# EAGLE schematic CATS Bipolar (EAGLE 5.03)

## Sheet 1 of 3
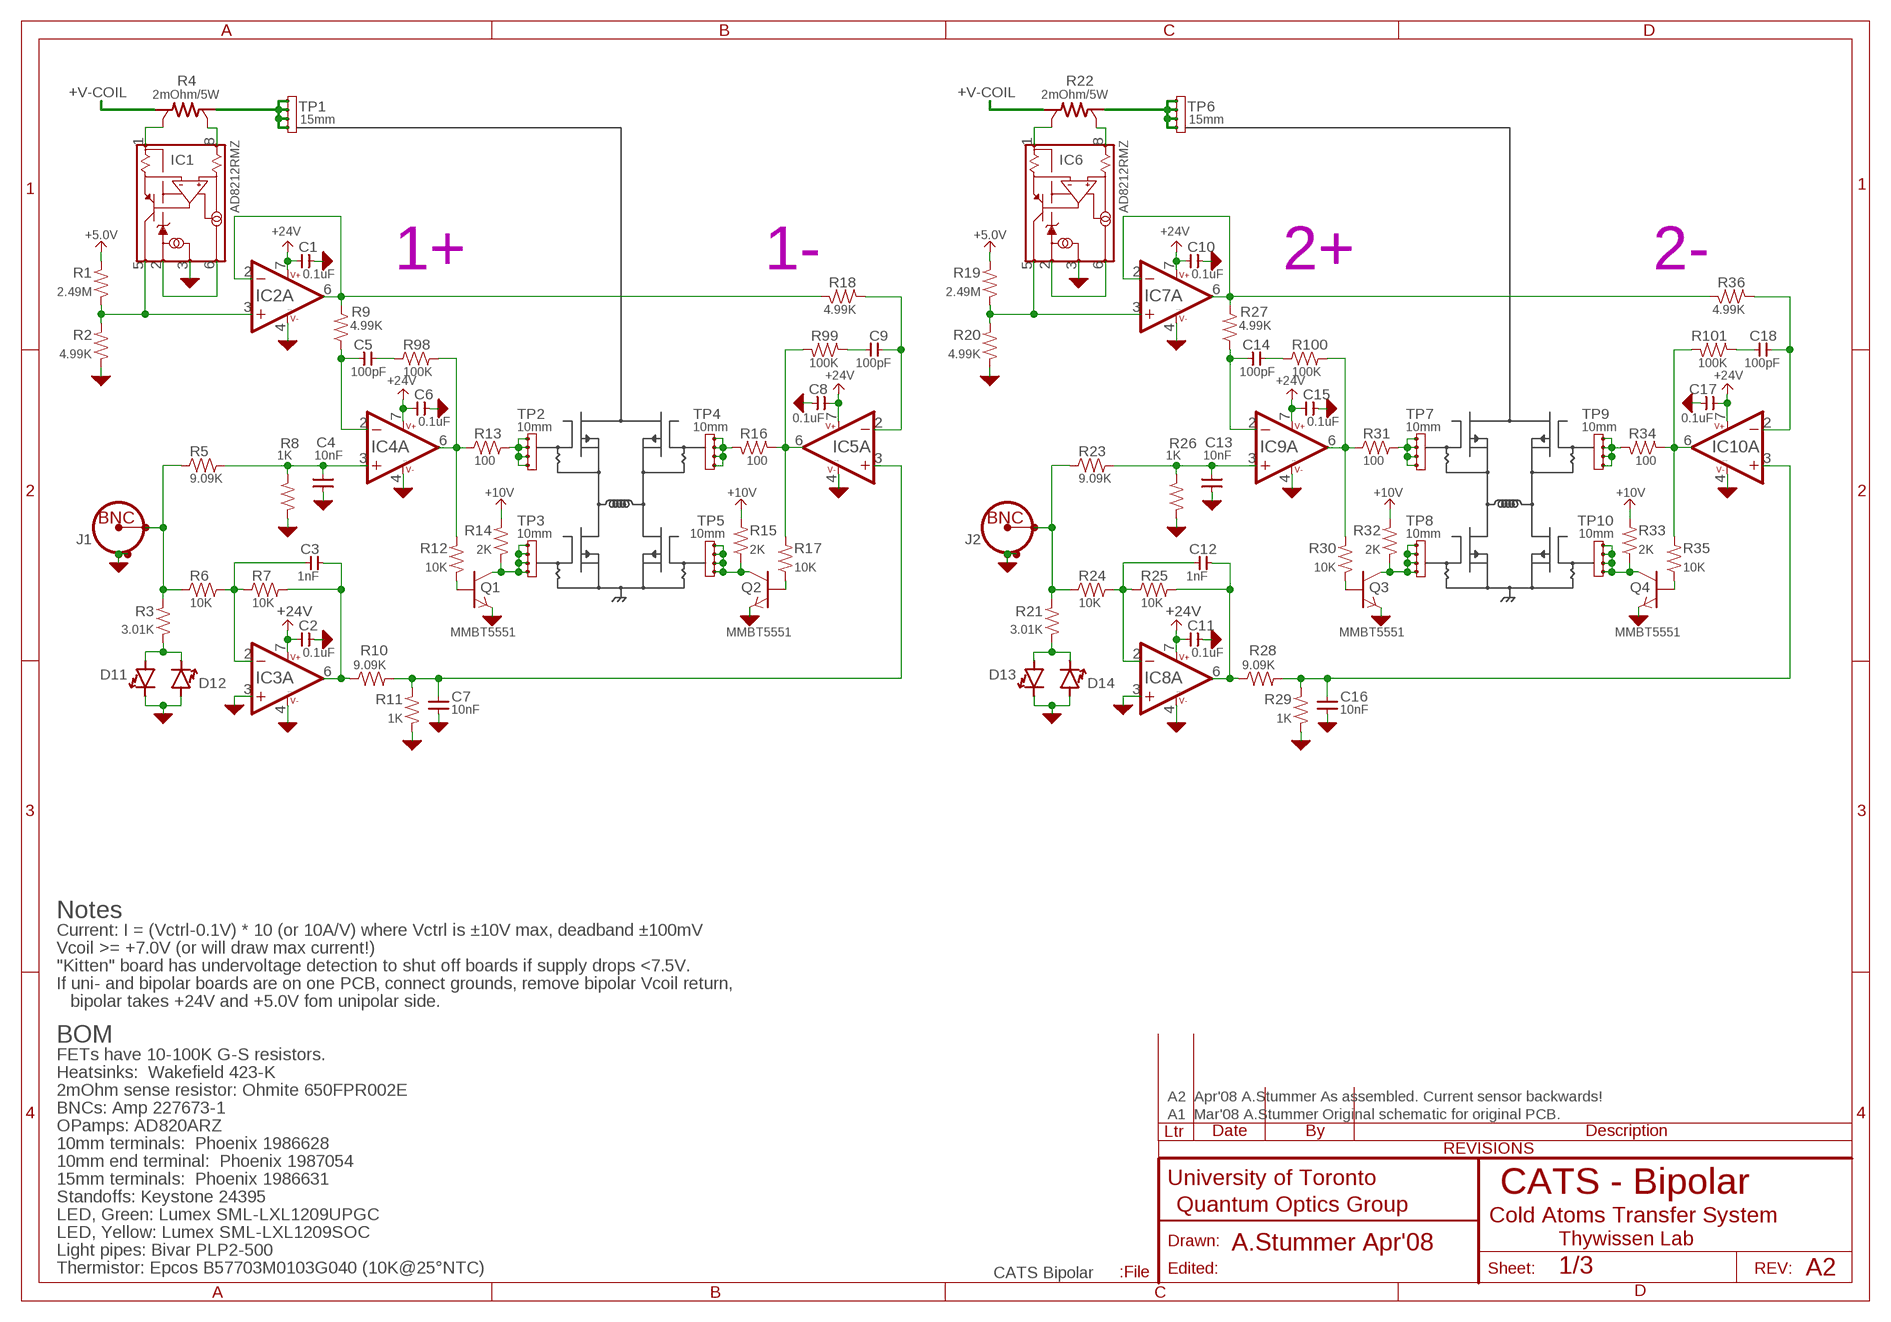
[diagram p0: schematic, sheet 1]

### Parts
C1  0.1uF  CAP-H-0805  [2012(0805)]
C2  0.1uF  CAP-H-0805  [2012(0805)]
C3  1nF  CAP-H-0805  [2012(0805)]
C4  10nF  CAP-V-0805  [2012(0805)]
C5  100pF  CAP-H-0805  [2012(0805)]
C6  0.1uF  CAP-H-0805  [2012(0805)]
C7  10nF  CAP-V-0805  [2012(0805)]
C8  0.1uF  CAP-H-0805  [2012(0805)]
C9  100pF  CAP-H-0805  [2012(0805)]
C10  0.1uF  CAP-H-0805  [2012(0805)]
C11  0.1uF  CAP-H-0805  [2012(0805)]
C12  1nF  CAP-H-0805  [2012(0805)]
C13  10nF  CAP-V-0805  [2012(0805)]
C14  100pF  CAP-H-0805  [2012(0805)]
C15  0.1uF  CAP-H-0805  [2012(0805)]
C16  10nF  CAP-V-0805  [2012(0805)]
C17  0.1uF  CAP-H-0805  [2012(0805)]
C18  100pF  CAP-H-0805  [2012(0805)]
D11  SML-LXL1209UPGC  LED-1209  [1209]
D12  SML-LXL1209SOC  LED-1209  [1209]
D13  SML-LXL1209UPGC  LED-1209  [1209]
D14  SML-LXL1209SOC  LED-1209  [1209]
IC1  AD8212RMZ  AD8212(CURRENT_MONITOR)RMZ  [MSOP8]
IC2  AD820ARZ  OPAMP-SO8  [SOIC-8]
IC3  AD820ARZ  OPAMP-SO8  [SOIC-8]
IC4  AD820ARZ  OPAMP-SO8  [SOIC-8]
IC5  AD820ARZ  OPAMP-SO8  [SOIC-8]
IC6  AD8212RMZ  AD8212(CURRENT_MONITOR)RMZ  [MSOP8]
IC7  AD820ARZ  OPAMP-SO8  [SOIC-8]
IC8  AD820ARZ  OPAMP-SO8  [SOIC-8]
IC9  AD820ARZ  OPAMP-SO8  [SOIC-8]
IC10  AD820ARZ  OPAMP-SO8  [SOIC-8]
J1  Amp 227673-1  CONN-BNC-TYPE1VERT  [CONN-BNC-AMP-TYPE1VERT]
J2  Amp 227673-1  CONN-BNC-TYPE1VERT  [CONN-BNC-AMP-TYPE1VERT]
Q1  MMBT5551  BJT-NPN-SOT23  [SOT23]
Q2  MMBT5551  BJT-NPN-SOT23  [SOT23]
Q3  MMBT5551  BJT-NPN-SOT23  [SOT23]
Q4  MMBT5551  BJT-NPN-SOT23  [SOT23]
R1  2.49M  R-V-0805  [2012(0805)]
R2  4.99K  R-V-0805  [2012(0805)]
R3  3.01K  R-H-0805  [2012(0805)]
R4  2mOhm/5W  R-SENSE-OHMITE_650  [OHMITE_650]
R5  9.09K  R-H-0805  [2012(0805)]
R6  10K  R-H-0805  [2012(0805)]
R7  10K  R-H-0805  [2012(0805)]
R8  1K  R-V-0805  [2012(0805)]
R9  4.99K  R-V-0805  [2012(0805)]
R10  9.09K  R-H-0805  [2012(0805)]
R11  1K  R-V-0805  [2012(0805)]
R12  10K  R-V-0805  [2012(0805)]
R13  100  R-H-0805  [2012(0805)]
R14  2K  R-V-0805  [2012(0805)]
R15  2K  R-V-0805  [2012(0805)]
R16  100  R-H-0805  [2012(0805)]
R17  10K  R-V-0805  [2012(0805)]
R18  4.99K  R-H-0805  [2012(0805)]
R19  2.49M  R-V-0805  [2012(0805)]
R20  4.99K  R-V-0805  [2012(0805)]
R21  3.01K  R-H-0805  [2012(0805)]
R22  2mOhm/5W  R-SENSE-OHMITE_650  [OHMITE_650]
R23  9.09K  R-H-0805  [2012(0805)]
R24  10K  R-H-0805  [2012(0805)]
R25  10K  R-H-0805  [2012(0805)]
R26  1K  R-V-0805  [2012(0805)]
R27  4.99K  R-V-0805  [2012(0805)]
R28  9.09K  R-H-0805  [2012(0805)]
R29  1K  R-V-0805  [2012(0805)]
R30  10K  R-V-0805  [2012(0805)]
R31  100  R-H-0805  [2012(0805)]
R32  2K  R-V-0805  [2012(0805)]
R33  2K  R-V-0805  [2012(0805)]
R34  100  R-H-0805  [2012(0805)]
R35  10K  R-V-0805  [2012(0805)]
R36  4.99K  R-H-0805  [2012(0805)]
R98  100K  R-H-0805  [2012(0805)]
R99  100K  R-H-0805  [2012(0805)]
R100  100K  R-H-0805  [2012(0805)]
R101  100K  R-H-0805  [2012(0805)]
TP1  Pheonix-1987631  TP4-ZFKDS(10MM)  [PHEONIX_ZFKDS-10/15MM-TERMINAL-BLOCK]
TP2  Pheonix-1987628  TP4-ZFKDS(10MM)  [PHEONIX_ZFKDS-10/15MM-TERMINAL-BLOCK]
TP3  Pheonix-1987628  TP4-ZFKDS(10MM)  [PHEONIX_ZFKDS-10/15MM-TERMINAL-BLOCK]
TP4  Pheonix-1987628  TP4-ZFKDS(10MM)  [PHEONIX_ZFKDS-10/15MM-TERMINAL-BLOCK]
TP5  Pheonix-1987628  TP4-ZFKDS(10MM)  [PHEONIX_ZFKDS-10/15MM-TERMINAL-BLOCK]
TP6  Pheonix-1987631  TP4-ZFKDS(10MM)  [PHEONIX_ZFKDS-10/15MM-TERMINAL-BLOCK]
TP7  Pheonix-1987628  TP4-ZFKDS(10MM)  [PHEONIX_ZFKDS-10/15MM-TERMINAL-BLOCK]
TP8  Pheonix-1987628  TP4-ZFKDS(10MM)  [PHEONIX_ZFKDS-10/15MM-TERMINAL-BLOCK]
TP9  Pheonix-1987628  TP4-ZFKDS(10MM)  [PHEONIX_ZFKDS-10/15MM-TERMINAL-BLOCK]
TP10  Pheonix-1987628  TP4-ZFKDS(10MM)  [PHEONIX_ZFKDS-10/15MM-TERMINAL-BLOCK]

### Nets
+5.0V: R1.2 R19.2 ; also sheet 2,3
+10V: R14.2 R15.2 R32.2 R33.2 ; also sheet 2,3
+24V: C1.1 C2.1 C6.1 C8.1 C10.1 C11.1 C15.1 C17.1 IC2.7(B:V+) IC3.7(B:V+) IC4.7(B:V+) IC5.7(B:V+) IC7.7(B:V+) IC8.7(B:V+) IC9.7(B:V+) IC10.7(B:V+) ; also sheet 2,3
+V-COIL [Power]: R4.CURRENT1 R22.CURRENT1 ; also sheet 2,3
AGND: C1.2 C2.2 C4.1 C6.2 C7.1 C8.2 C10.2 C11.2 C13.1 C15.2 C16.1 C17.2 D11.K(C) D12.A D13.K(C) D14.A IC1.3(BIAS) IC2.4(B:V-) IC3.3(A:+IN) IC3.4(B:V-) IC4.4(B:V-) IC5.4(B:V-) IC6.3(BIAS) IC7.4(B:V-) IC8.3(A:+IN) IC8.4(B:V-) IC9.4(B:V-) IC10.4(B:V-) J1.SHIELD1 J1.SHIELD2 J2.SHIELD1 J2.SHIELD2 Q1.2(E) Q2.2(E) Q3.2(E) Q4.2(E) R2.1 R8.1 R11.1 R20.1 R26.1 R29.1 ; also sheet 2,3
N$1: IC1.5(I-OUT) IC2.3(A:+IN) R1.1 R2.2
N$2: IC2.2(A:-IN) IC2.6(A:OUT) R9.2 R18.2
N$3: IC1.1(V+) R4.SENSE1
N$4: IC1.8(V-SENSE) R4.SENSE2
N$5: IC1.2(COM) IC1.6(ALPHA)
N$6: J1.CONDUCTOR R3.2 R5.1 R6.1
N$7: C9.1 IC5.2(A:-IN) R18.1
N$8 [Power]: R4.CURRENT2 TP1.T@1(T) TP1.T@2(T) TP1.T@3(T) TP1.T@4(T)
N$9: IC5.6(A:OUT) R16.1 R17.2 R99.2
N$10: R16.2 TP4.T@1(T) TP4.T@2(T) TP4.T@3(T) TP4.T@4(T)
N$11: C3.2 IC3.6(A:OUT) R7.2 R10.1
N$12: C3.1 IC3.2(A:-IN) R6.2 R7.1
N$13: C7.2 IC5.3(A:+IN) R10.2 R11.2
N$14: Q1.3(C) R14.1 TP3.T@1(T) TP3.T@2(T) TP3.T@3(T) TP3.T@4(T)
N$15: Q1.1(B) R12.1
N$16: C13.2 IC9.3(A:+IN) R23.2 R26.2
N$17: Q2.3(C) R15.1 TP5.T@1(T) TP5.T@2(T) TP5.T@3(T) TP5.T@4(T)
N$18: Q2.1(B) R17.1
N$19: C14.1 IC9.2(A:-IN) R27.1
N$20: IC9.6(A:OUT) R30.2 R31.1 R100.2
N$21: R31.2 TP7.T@1(T) TP7.T@2(T) TP7.T@3(T) TP7.T@4(T)
N$22: D13.A D14.K(C) R21.1
N$23: IC6.1(V+) R22.SENSE1
N$24: IC6.8(V-SENSE) R22.SENSE2
N$25: IC6.2(COM) IC6.6(ALPHA)
N$26 [Power]: R22.CURRENT2 TP6.T@1(T) TP6.T@2(T) TP6.T@3(T) TP6.T@4(T)
N$27: IC6.5(I-OUT) IC7.3(A:+IN) R19.1 R20.2
N$28: IC7.2(A:-IN) IC7.6(A:OUT) R27.2 R36.2
N$29: C18.1 IC10.2(A:-IN) R36.1
N$30: IC10.6(A:OUT) R34.1 R35.2 R101.2
N$31: R34.2 TP9.T@1(T) TP9.T@2(T) TP9.T@3(T) TP9.T@4(T)
N$32: C12.2 IC8.6(A:OUT) R25.2 R28.1
N$33: C12.1 IC8.2(A:-IN) R24.2 R25.1
N$34: J2.CONDUCTOR R21.2 R23.1 R24.1
N$35: C16.2 IC10.3(A:+IN) R28.2 R29.2
N$36: Q3.3(C) R32.1 TP8.T@1(T) TP8.T@2(T) TP8.T@3(T) TP8.T@4(T)
N$37: Q3.1(B) R30.1
N$38: Q4.3(C) R33.1 TP10.T@1(T) TP10.T@2(T) TP10.T@3(T) TP10.T@4(T)
N$39: Q4.1(B) R35.1
N$110: C4.2 IC4.3(A:+IN) R5.2 R8.2
N$114: C5.1 IC4.2(A:-IN) R9.1
N$115: IC4.6(A:OUT) R12.2 R13.1 R98.2
N$117: R13.2 TP2.T@1(T) TP2.T@2(T) TP2.T@3(T) TP2.T@4(T)
N$121: D11.A D12.K(C) R3.1
N$122: C5.2 R98.1
N$123: C9.2 R99.1
N$124: C14.2 R100.1
N$125: C18.2 R101.1

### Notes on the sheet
- 15mm | 15mm
- 1+ | 1- | 2+ | 2-
- 10mm | 10mm | 10mm | 10mm
- 10mm | 10mm | 10mm | 10mm
- Notes
- Current: I = (Vctrl-0.1V) * 10 (or 10A/V) where Vctrl is ±10V max, deadband ±100mV
- Vcoil >= +7.0V (or will draw max current!)
- "Kitten" board has undervoltage detection to shut off boards if supply drops <7.5V.
- If uni- and bipolar boards are on one PCB, connect grounds, remove bipolar Vcoil return,
- bipolar takes +24V and +5.0V fom unipolar side.
- BOM
- FETs have 10-100K G-S resistors.
- Heatsinks:  Wakefield 423-K
- 2mOhm sense resistor: Ohmite 650FPR002E
- A2  Apr'08 A.Stummer As assembled. Current sensor backwards!
- BNCs: Amp 227673-1
- A1  Mar'08 A.Stummer Original schematic for original PCB.
- OPamps: AD820ARZ
- 10mm terminals:  Phoenix 1986628
- 10mm end terminal:  Phoenix 1987054
- 15mm terminals:  Phoenix 1986631
- CATS - Bipolar
- Standoffs: Keystone 24395
- LED, Green: Lumex SML-LXL1209UPGC | Cold Atoms Transfer System
- LED, Yellow: Lumex SML-LXL1209SOC
- A.Stummer Apr'08 | Thywissen Lab
- Light pipes: Bivar PLP2-500
- Thermistor: Epcos B57703M0103G040 (10K@25°NTC) | A2

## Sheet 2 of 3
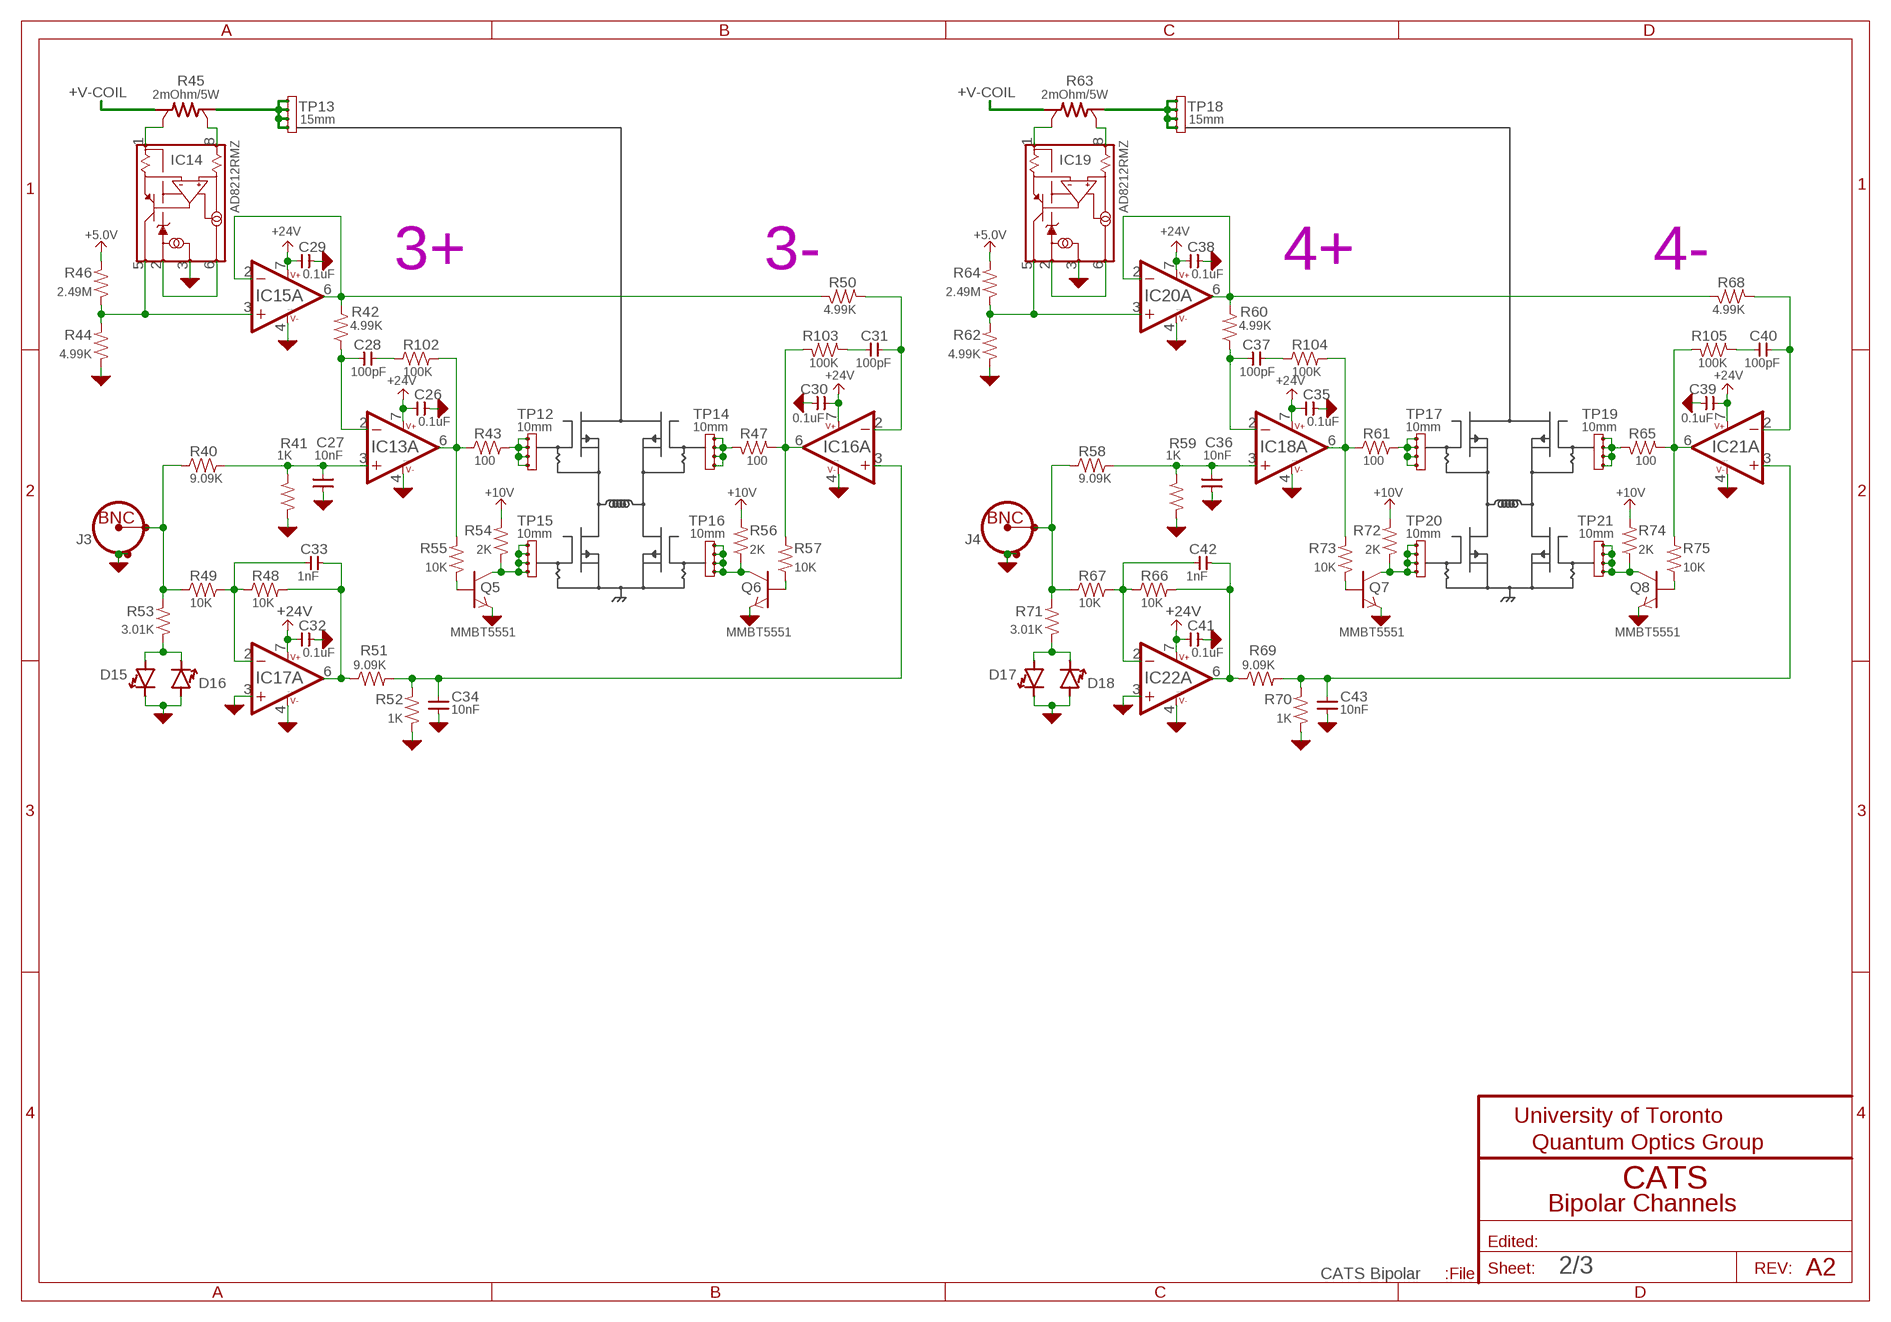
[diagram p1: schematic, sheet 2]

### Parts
C26  0.1uF  CAP-H-0805  [2012(0805)]
C27  10nF  CAP-V-0805  [2012(0805)]
C28  100pF  CAP-H-0805  [2012(0805)]
C29  0.1uF  CAP-H-0805  [2012(0805)]
C30  0.1uF  CAP-H-0805  [2012(0805)]
C31  100pF  CAP-H-0805  [2012(0805)]
C32  0.1uF  CAP-H-0805  [2012(0805)]
C33  1nF  CAP-H-0805  [2012(0805)]
C34  10nF  CAP-V-0805  [2012(0805)]
C35  0.1uF  CAP-H-0805  [2012(0805)]
C36  10nF  CAP-V-0805  [2012(0805)]
C37  100pF  CAP-H-0805  [2012(0805)]
C38  0.1uF  CAP-H-0805  [2012(0805)]
C39  0.1uF  CAP-H-0805  [2012(0805)]
C40  100pF  CAP-H-0805  [2012(0805)]
C41  0.1uF  CAP-H-0805  [2012(0805)]
C42  1nF  CAP-H-0805  [2012(0805)]
C43  10nF  CAP-V-0805  [2012(0805)]
D15  SML-LXL1209UPGC  LED-1209  [1209]
D16  SML-LXL1209SOC  LED-1209  [1209]
D17  SML-LXL1209UPGC  LED-1209  [1209]
D18  SML-LXL1209SOC  LED-1209  [1209]
IC13  AD820ARZ  OPAMP-SO8  [SOIC-8]
IC14  AD8212RMZ  AD8212(CURRENT_MONITOR)RMZ  [MSOP8]
IC15  AD820ARZ  OPAMP-SO8  [SOIC-8]
IC16  AD820ARZ  OPAMP-SO8  [SOIC-8]
IC17  AD820ARZ  OPAMP-SO8  [SOIC-8]
IC18  AD820ARZ  OPAMP-SO8  [SOIC-8]
IC19  AD8212RMZ  AD8212(CURRENT_MONITOR)RMZ  [MSOP8]
IC20  AD820ARZ  OPAMP-SO8  [SOIC-8]
IC21  AD820ARZ  OPAMP-SO8  [SOIC-8]
IC22  AD820ARZ  OPAMP-SO8  [SOIC-8]
J3  Amp 227673-1  CONN-BNC-TYPE1VERT  [CONN-BNC-AMP-TYPE1VERT]
J4  Amp 227673-1  CONN-BNC-TYPE1VERT  [CONN-BNC-AMP-TYPE1VERT]
Q5  MMBT5551  BJT-NPN-SOT23  [SOT23]
Q6  MMBT5551  BJT-NPN-SOT23  [SOT23]
Q7  MMBT5551  BJT-NPN-SOT23  [SOT23]
Q8  MMBT5551  BJT-NPN-SOT23  [SOT23]
R40  9.09K  R-H-0805  [2012(0805)]
R41  1K  R-V-0805  [2012(0805)]
R42  4.99K  R-V-0805  [2012(0805)]
R43  100  R-H-0805  [2012(0805)]
R44  4.99K  R-V-0805  [2012(0805)]
R45  2mOhm/5W  R-SENSE-OHMITE_650  [OHMITE_650]
R46  2.49M  R-V-0805  [2012(0805)]
R47  100  R-H-0805  [2012(0805)]
R48  10K  R-H-0805  [2012(0805)]
R49  10K  R-H-0805  [2012(0805)]
R50  4.99K  R-H-0805  [2012(0805)]
R51  9.09K  R-H-0805  [2012(0805)]
R52  1K  R-V-0805  [2012(0805)]
R53  3.01K  R-H-0805  [2012(0805)]
R54  2K  R-V-0805  [2012(0805)]
R55  10K  R-V-0805  [2012(0805)]
R56  2K  R-V-0805  [2012(0805)]
R57  10K  R-V-0805  [2012(0805)]
R58  9.09K  R-H-0805  [2012(0805)]
R59  1K  R-V-0805  [2012(0805)]
R60  4.99K  R-V-0805  [2012(0805)]
R61  100  R-H-0805  [2012(0805)]
R62  4.99K  R-V-0805  [2012(0805)]
R63  2mOhm/5W  R-SENSE-OHMITE_650  [OHMITE_650]
R64  2.49M  R-V-0805  [2012(0805)]
R65  100  R-H-0805  [2012(0805)]
R66  10K  R-H-0805  [2012(0805)]
R67  10K  R-H-0805  [2012(0805)]
R68  4.99K  R-H-0805  [2012(0805)]
R69  9.09K  R-H-0805  [2012(0805)]
R70  1K  R-V-0805  [2012(0805)]
R71  3.01K  R-H-0805  [2012(0805)]
R72  2K  R-V-0805  [2012(0805)]
R73  10K  R-V-0805  [2012(0805)]
R74  2K  R-V-0805  [2012(0805)]
R75  10K  R-V-0805  [2012(0805)]
R102  100K  R-H-0805  [2012(0805)]
R103  100K  R-H-0805  [2012(0805)]
R104  100K  R-H-0805  [2012(0805)]
R105  100K  R-H-0805  [2012(0805)]
TP12  Pheonix-1987628  TP4-ZFKDS(10MM)  [PHEONIX_ZFKDS-10/15MM-TERMINAL-BLOCK]
TP13  Pheonix-1987631  TP4-ZFKDS(10MM)  [PHEONIX_ZFKDS-10/15MM-TERMINAL-BLOCK]
TP14  Pheonix-1987628  TP4-ZFKDS(10MM)  [PHEONIX_ZFKDS-10/15MM-TERMINAL-BLOCK]
TP15  Pheonix-1987628  TP4-ZFKDS(10MM)  [PHEONIX_ZFKDS-10/15MM-TERMINAL-BLOCK]
TP16  Pheonix-1987628  TP4-ZFKDS(10MM)  [PHEONIX_ZFKDS-10/15MM-TERMINAL-BLOCK]
TP17  Pheonix-1987628  TP4-ZFKDS(10MM)  [PHEONIX_ZFKDS-10/15MM-TERMINAL-BLOCK]
TP18  Pheonix-1987631  TP4-ZFKDS(10MM)  [PHEONIX_ZFKDS-10/15MM-TERMINAL-BLOCK]
TP19  Pheonix-1987628  TP4-ZFKDS(10MM)  [PHEONIX_ZFKDS-10/15MM-TERMINAL-BLOCK]
TP20  Pheonix-1987628  TP4-ZFKDS(10MM)  [PHEONIX_ZFKDS-10/15MM-TERMINAL-BLOCK]
TP21  Pheonix-1987628  TP4-ZFKDS(10MM)  [PHEONIX_ZFKDS-10/15MM-TERMINAL-BLOCK]

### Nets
+5.0V: R46.2 R64.2 ; also sheet 1,3
+10V: R54.2 R56.2 R72.2 R74.2 ; also sheet 1,3
+24V: C26.1 C29.1 C30.1 C32.1 C35.1 C38.1 C39.1 C41.1 IC13.7(B:V+) IC15.7(B:V+) IC16.7(B:V+) IC17.7(B:V+) IC18.7(B:V+) IC20.7(B:V+) IC21.7(B:V+) IC22.7(B:V+) ; also sheet 1,3
+V-COIL [Power]: R45.CURRENT1 R63.CURRENT1 ; also sheet 1,3
AGND: C26.2 C27.1 C29.2 C30.2 C32.2 C34.1 C35.2 C36.1 C38.2 C39.2 C41.2 C43.1 D15.K(C) D16.A D17.K(C) D18.A IC13.4(B:V-) IC14.3(BIAS) IC15.4(B:V-) IC16.4(B:V-) IC17.3(A:+IN) IC17.4(B:V-) IC18.4(B:V-) IC19.3(BIAS) IC20.4(B:V-) IC21.4(B:V-) IC22.3(A:+IN) IC22.4(B:V-) J3.SHIELD1 J3.SHIELD2 J4.SHIELD1 J4.SHIELD2 Q5.2(E) Q6.2(E) Q7.2(E) Q8.2(E) R41.1 R44.1 R52.1 R59.1 R62.1 R70.1 ; also sheet 1,3
N$40: C27.2 IC13.3(A:+IN) R40.2 R41.2
N$41: C28.1 IC13.2(A:-IN) R42.1
N$42: IC13.6(A:OUT) R43.1 R55.2 R102.2
N$43: R43.2 TP12.T@1(T) TP12.T@2(T) TP12.T@3(T) TP12.T@4(T)
N$44: D15.A D16.K(C) R53.1
N$45: IC14.1(V+) R45.SENSE1
N$46: IC14.8(V-SENSE) R45.SENSE2
N$47: IC14.2(COM) IC14.6(ALPHA)
N$48 [Power]: R45.CURRENT2 TP13.T@1(T) TP13.T@2(T) TP13.T@3(T) TP13.T@4(T)
N$49: IC14.5(I-OUT) IC15.3(A:+IN) R44.2 R46.1
N$50: IC15.2(A:-IN) IC15.6(A:OUT) R42.2 R50.2
N$51: C31.1 IC16.2(A:-IN) R50.1
N$52: IC16.6(A:OUT) R47.1 R57.2 R103.2
N$53: R47.2 TP14.T@1(T) TP14.T@2(T) TP14.T@3(T) TP14.T@4(T)
N$54: C33.2 IC17.6(A:OUT) R48.2 R51.1
N$55: C33.1 IC17.2(A:-IN) R48.1 R49.2
N$56: J3.CONDUCTOR R40.1 R49.1 R53.2
N$57: C34.2 IC16.3(A:+IN) R51.2 R52.2
N$58: Q5.3(C) R54.1 TP15.T@1(T) TP15.T@2(T) TP15.T@3(T) TP15.T@4(T)
N$59: Q5.1(B) R55.1
N$60: Q6.3(C) R56.1 TP16.T@1(T) TP16.T@2(T) TP16.T@3(T) TP16.T@4(T)
N$61: Q6.1(B) R57.1
N$62: C36.2 IC18.3(A:+IN) R58.2 R59.2
N$63: C37.1 IC18.2(A:-IN) R60.1
N$64: IC18.6(A:OUT) R61.1 R73.2 R104.2
N$65: R61.2 TP17.T@1(T) TP17.T@2(T) TP17.T@3(T) TP17.T@4(T)
N$66: D17.A D18.K(C) R71.1
N$67: IC19.1(V+) R63.SENSE1
N$68: IC19.8(V-SENSE) R63.SENSE2
N$69: IC19.2(COM) IC19.6(ALPHA)
N$70 [Power]: R63.CURRENT2 TP18.T@1(T) TP18.T@2(T) TP18.T@3(T) TP18.T@4(T)
N$71: IC19.5(I-OUT) IC20.3(A:+IN) R62.2 R64.1
N$72: IC20.2(A:-IN) IC20.6(A:OUT) R60.2 R68.2
N$73: C40.1 IC21.2(A:-IN) R68.1
N$74: IC21.6(A:OUT) R65.1 R75.2 R105.2
N$75: R65.2 TP19.T@1(T) TP19.T@2(T) TP19.T@3(T) TP19.T@4(T)
N$76: C42.2 IC22.6(A:OUT) R66.2 R69.1
N$77: C42.1 IC22.2(A:-IN) R66.1 R67.2
N$78: J4.CONDUCTOR R58.1 R67.1 R71.2
N$79: C43.2 IC21.3(A:+IN) R69.2 R70.2
N$80: Q7.3(C) R72.1 TP20.T@1(T) TP20.T@2(T) TP20.T@3(T) TP20.T@4(T)
N$81: Q7.1(B) R73.1
N$82: Q8.3(C) R74.1 TP21.T@1(T) TP21.T@2(T) TP21.T@3(T) TP21.T@4(T)
N$83: Q8.1(B) R75.1
N$126: C28.2 R102.1
N$127: C31.2 R103.1
N$128: C37.2 R104.1
N$129: C40.2 R105.1

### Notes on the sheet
- 15mm | 15mm
- 3+ | 3- | 4+ | 4-
- 10mm | 10mm | 10mm | 10mm
- 10mm | 10mm | 10mm | 10mm
- CATS
- Bipolar Channels
- A2

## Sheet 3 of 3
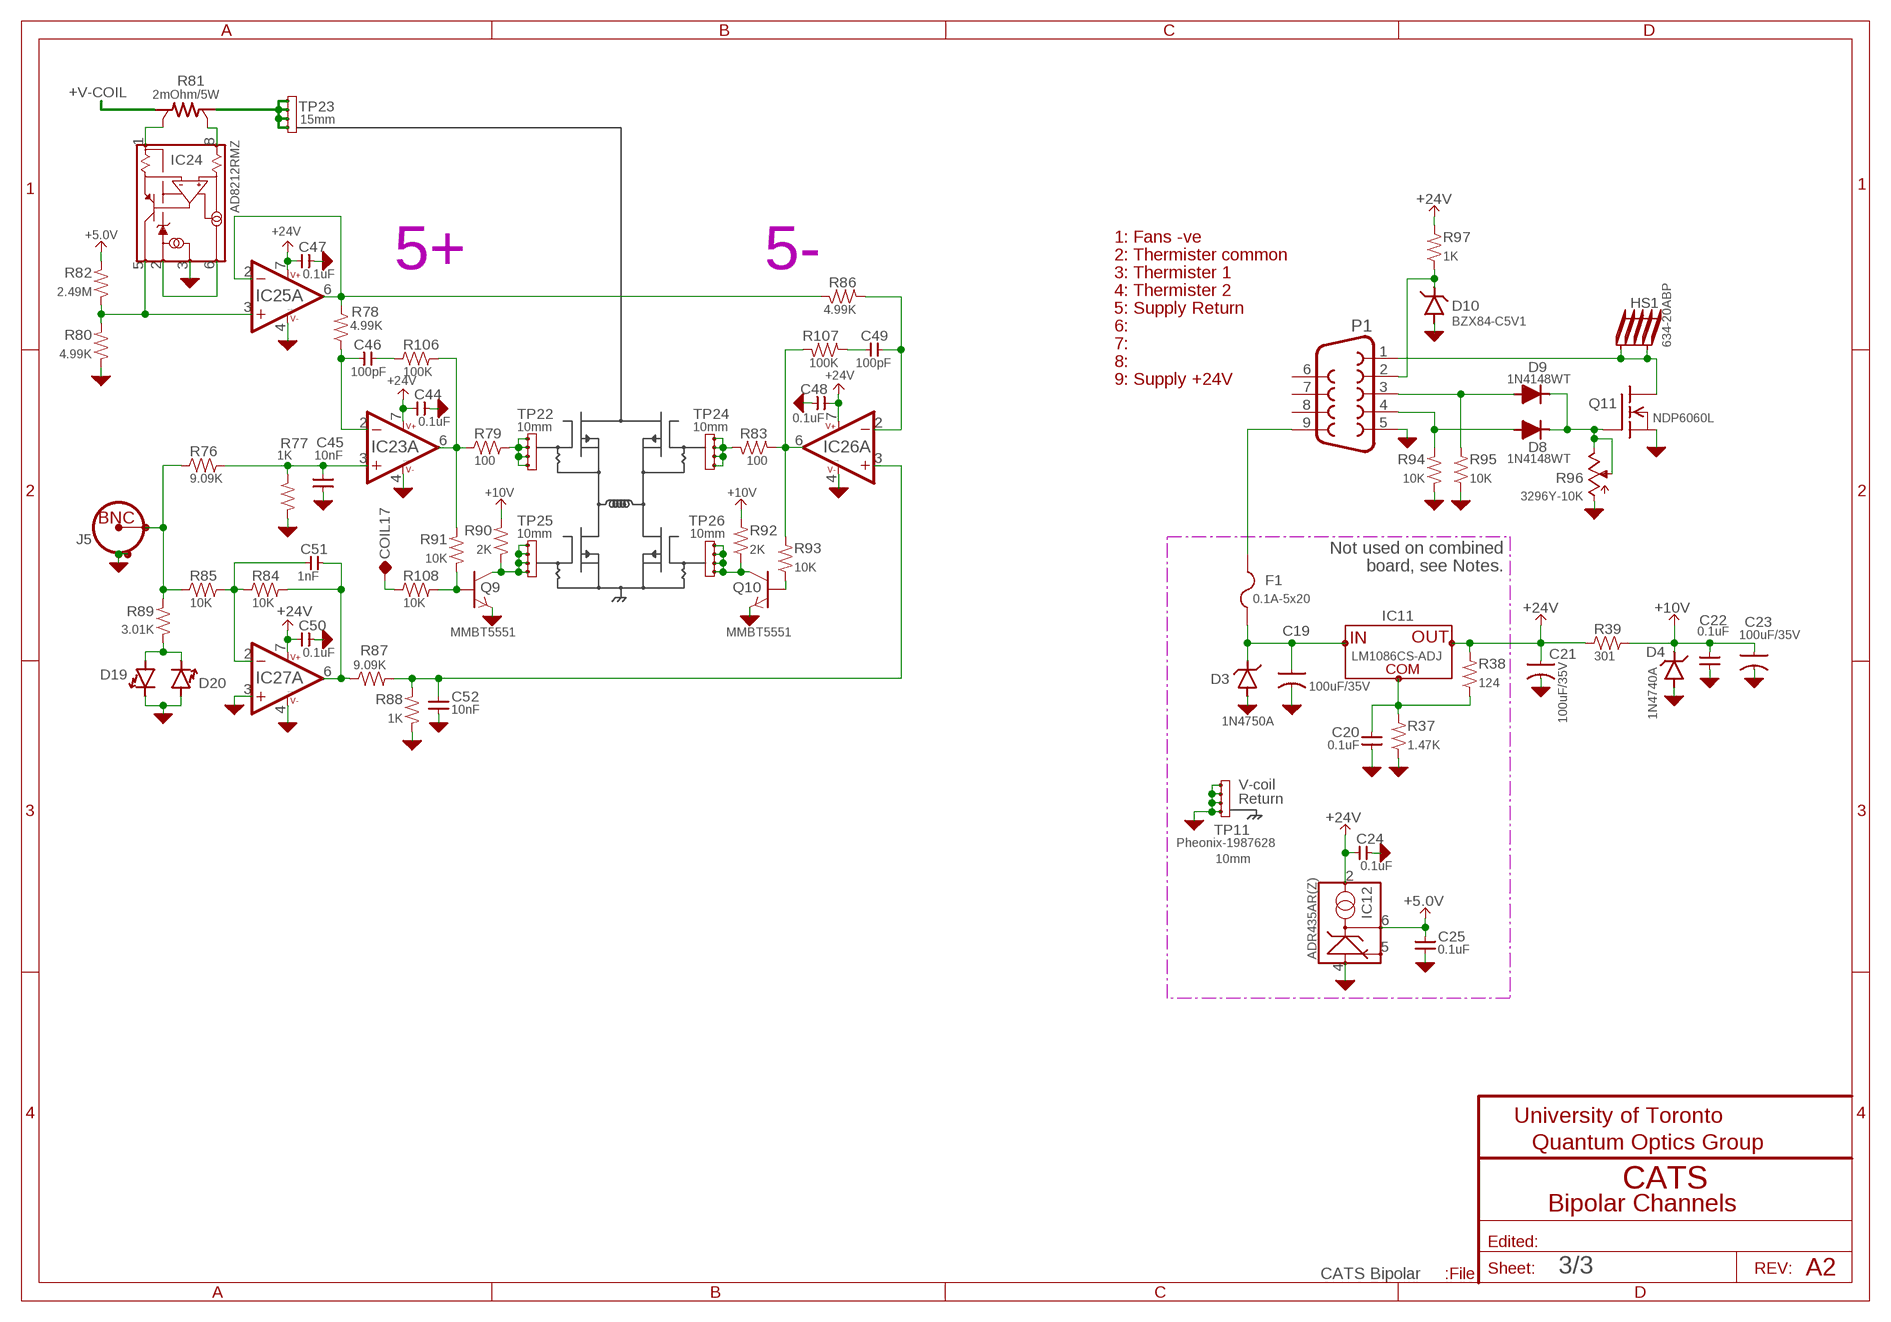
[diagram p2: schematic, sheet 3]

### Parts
C19  100uF/35V  CAP-POL-EIA-A  [EIA-A]
C20  0.1uF  CAP-V-0805  [2012(0805)]
C21  100uF/35V  CAP-POL-EIA-A  [EIA-A]
C22  0.1uF  CAP-V-0805  [2012(0805)]
C23  100uF/35V  CAP-POL-EIA-A  [EIA-A]
C24  0.1uF  CAP-H-0805  [2012(0805)]
C25  0.1uF  CAP-V-0805  [2012(0805)]
C44  0.1uF  CAP-H-0805  [2012(0805)]
C45  10nF  CAP-V-0805  [2012(0805)]
C46  100pF  CAP-H-0805  [2012(0805)]
C47  0.1uF  CAP-H-0805  [2012(0805)]
C48  0.1uF  CAP-H-0805  [2012(0805)]
C49  100pF  CAP-H-0805  [2012(0805)]
C50  0.1uF  CAP-H-0805  [2012(0805)]
C51  1nF  CAP-H-0805  [2012(0805)]
C52  10nF  CAP-V-0805  [2012(0805)]
COIL17  TP-0.042"  [TP-0.042]
D3  1N4750A  ZENER-THROUGH-0.4"  [PASSIVE_0.4"]
D4  1N4740A  ZENER-THROUGH-0.4"  [PASSIVE_0.4"]
D8  1N4148WT  [SOD523]
D9  1N4148WT  [SOD523]
D10  BZX84-C5V1  ZENER-SOT23  [SOT23]
D19  SML-LXL1209UPGC  LED-1209  [1209]
D20  SML-LXL1209SOC  LED-1209  [1209]
F1  0.1A-5x20  FUSE-5X20-4  [FUSE]
HS1  634-20ABP  HEATSINK-5(TO220)  [HEATSINK-5(TO-220)]
IC11  LM1086CS-ADJ  LM1086-TO263  [TO263]
IC12  ADR435AR(Z)  ADR43_(REFERENCE)-SOIC8  [SOIC-8]
IC23  AD820ARZ  OPAMP-SO8  [SOIC-8]
IC24  AD8212RMZ  AD8212(CURRENT_MONITOR)RMZ  [MSOP8]
IC25  AD820ARZ  OPAMP-SO8  [SOIC-8]
IC26  AD820ARZ  OPAMP-SO8  [SOIC-8]
IC27  AD820ARZ  OPAMP-SO8  [SOIC-8]
J5  Amp 227673-1  CONN-BNC-TYPE1VERT  [CONN-BNC-AMP-TYPE1VERT]
P1  CONN-DB9H  [CONN-DB9-HORIZ1]
Q9  MMBT5551  BJT-NPN-SOT23  [SOT23]
Q10  MMBT5551  BJT-NPN-SOT23  [SOT23]
Q11  NDP6060L  MOSFET-N-TO220-VERT  [TO220-VERTICAL]
R37  1.47K  R-V-0805  [2012(0805)]
R38  124  R-V-0805  [2012(0805)]
R39  301  R-H-0805  [2012(0805)]
R76  9.09K  R-H-0805  [2012(0805)]
R77  1K  R-V-0805  [2012(0805)]
R78  4.99K  R-V-0805  [2012(0805)]
R79  100  R-H-0805  [2012(0805)]
R80  4.99K  R-V-0805  [2012(0805)]
R81  2mOhm/5W  R-SENSE-OHMITE_650  [OHMITE_650]
R82  2.49M  R-V-0805  [2012(0805)]
R83  100  R-H-0805  [2012(0805)]
R84  10K  R-H-0805  [2012(0805)]
R85  10K  R-H-0805  [2012(0805)]
R86  4.99K  R-H-0805  [2012(0805)]
R87  9.09K  R-H-0805  [2012(0805)]
R88  1K  R-V-0805  [2012(0805)]
R89  3.01K  R-H-0805  [2012(0805)]
R90  2K  R-V-0805  [2012(0805)]
R91  10K  R-V-0805  [2012(0805)]
R92  2K  R-V-0805  [2012(0805)]
R93  10K  R-V-0805  [2012(0805)]
R94  10K  R-V-0805  [2012(0805)]
R95  10K  R-V-0805  [2012(0805)]
R96  3296Y-10K  POTBOURNS_3296Y  [BOURNS-3296Y]
R97  1K  R-V-0805  [2012(0805)]
R106  100K  R-H-0805  [2012(0805)]
R107  100K  R-H-0805  [2012(0805)]
R108  10K  R-H-0805  [2012(0805)]
TP11  Pheonix-1987628  TP4-ZFKDS(10MM)  [PHEONIX_ZFKDS-10/15MM-TERMINAL-BLOCK]
TP22  Pheonix-1987628  TP4-ZFKDS(10MM)  [PHEONIX_ZFKDS-10/15MM-TERMINAL-BLOCK]
TP23  Pheonix-1987631  TP4-ZFKDS(10MM)  [PHEONIX_ZFKDS-10/15MM-TERMINAL-BLOCK]
TP24  Pheonix-1987628  TP4-ZFKDS(10MM)  [PHEONIX_ZFKDS-10/15MM-TERMINAL-BLOCK]
TP25  Pheonix-1987628  TP4-ZFKDS(10MM)  [PHEONIX_ZFKDS-10/15MM-TERMINAL-BLOCK]
TP26  Pheonix-1987628  TP4-ZFKDS(10MM)  [PHEONIX_ZFKDS-10/15MM-TERMINAL-BLOCK]

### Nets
+5.0V: C25.2 IC12.6(OUT) R82.2 ; also sheet 1,2
+10V: C22.2 C23.2(POS) D4.2(C) R39.2 R90.2 R92.2 ; also sheet 1,2
+24V: C21.2(POS) C24.1 C44.1 C47.1 C48.1 C50.1 IC11.2(OUT) IC12.2(VIN) IC23.7(B:V+) IC25.7(B:V+) IC26.7(B:V+) IC27.7(B:V+) R38.2 R39.1 R97.2 ; also sheet 1,2
+V-COIL [Power]: R81.CURRENT1 ; also sheet 1,2
AGND: C19.1(NEG) C20.1 C21.1(NEG) C22.1 C23.1(NEG) C24.2 C25.1 C44.2 C45.1 C47.2 C48.2 C50.2 C52.1 D3.1(A) D4.1(A) D10.1(A) D19.K(C) D20.A IC12.4(COM) IC23.4(B:V-) IC24.3(BIAS) IC25.4(B:V-) IC26.4(B:V-) IC27.3(A:+IN) IC27.4(B:V-) J5.SHIELD1 J5.SHIELD2 P1.5 Q9.2(E) Q10.2(E) Q11.3(S) R37.1 R77.1 R80.1 R88.1 R94.1 R95.1 R96.CCW TP11.T@1(T) TP11.T@2(T) TP11.T@3(T) TP11.T@4(T) ; also sheet 1,2
N$84: C45.2 IC23.3(A:+IN) R76.2 R77.2
N$85: C46.1 IC23.2(A:-IN) R78.1
N$86: IC23.6(A:OUT) R79.1 R91.2 R106.2
N$87: R79.2 TP22.T@1(T) TP22.T@2(T) TP22.T@3(T) TP22.T@4(T)
N$88: D19.A D20.K(C) R89.1
N$89: IC24.1(V+) R81.SENSE1
N$90: IC24.8(V-SENSE) R81.SENSE2
N$91: IC24.2(COM) IC24.6(ALPHA)
N$92 [Power]: R81.CURRENT2 TP23.T@1(T) TP23.T@2(T) TP23.T@3(T) TP23.T@4(T)
N$93: IC24.5(I-OUT) IC25.3(A:+IN) R80.2 R82.1
N$94: IC25.2(A:-IN) IC25.6(A:OUT) R78.2 R86.2
N$95: C49.1 IC26.2(A:-IN) R86.1
N$96: IC26.6(A:OUT) R83.1 R93.2 R107.2
N$97: R83.2 TP24.T@1(T) TP24.T@2(T) TP24.T@3(T) TP24.T@4(T)
N$98: C51.2 IC27.6(A:OUT) R84.2 R87.1
N$99: C51.1 IC27.2(A:-IN) R84.1 R85.2
N$100: J5.CONDUCTOR R76.1 R85.1 R89.2
N$101: C52.2 IC26.3(A:+IN) R87.2 R88.2
N$102: Q9.3(C) R90.1 TP25.T@1(T) TP25.T@2(T) TP25.T@3(T) TP25.T@4(T)
N$103: Q9.1(B) R91.1 R108.2
N$104: Q10.3(C) R92.1 TP26.T@1(T) TP26.T@2(T) TP26.T@3(T) TP26.T@4(T)
N$105: Q10.1(B) R93.1
N$112: F1.1A P1.9
N$113: D8.A P1.4 R94.2
N$116: HS1.1 HS1.2 P1.1 Q11.2(D)
N$118: D8.C D9.C Q11.1(G) R96.CW R96.W
N$119: D9.A P1.3 R95.2
N$120: D10.3(C) P1.2 R97.1
N$130: C46.2 R106.1
N$131: C49.2 R107.1
N$132: COIL17.TP R108.1
N$145: C19.2(POS) D3.2(C) F1.2A IC11.3(VI)
N$146: C20.2 IC11.1(COM) R37.2 R38.1
Unconnected: IC12.5(TRIM) P1.6 P1.7 P1.8

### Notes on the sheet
- 15mm
- 1: Fans -ve
- 2: Thermister common
- 5+ | 5-
- 3: Thermister 1
- 4: Thermister 2
- 5: Supply Return
- 6:
- 7:
- 8:
- 9: Supply +24V
- 10mm | 10mm
- 10mm | 10mm | Not used on combined
- board, see Notes.
- V-coil
- Return
- 10mm
- CATS
- Bipolar Channels
- A2

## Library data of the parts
C1-C3 C5 C6 C8-C12 C14 C15 C17 C18 C24 C26 C28-C33 C35 C37-C42 C44 C46-C51 = QuantumOptics:CAP-H-: Cap, SMT and Through-hole, 0402 and up.
C4 C7 C13 C16 C20 C22 C25 C27 C34 C36 C43 C45 C52 = QuantumOptics:CAP-V-: Cap, SMT and Through-hole, 0402 and up.
C19 C21 C23 = QuantumOptics:CAP-POL-: Capacitor, Polarized, SMT 0805 and up, probably tantalum.
COIL17 = QuantumOptics:TP: Testpoint, test point on schematic, on PCB either SMT pad, small hole or loop style TP.
D3 D4 D10 = QuantumOptics:ZENER: Zener
D8 D9 = QuantumOptics:1N4148: 1N4148, fast small signal silicon, 80V 125mAavg trr=4nSmax
D11-D20 = QuantumOptics:LED: LED
F1 = QuantumOptics:FUSE: Fuse
HS1 = QuantumOptics:HEATSINK-5(TO220): Heatsink, TO-220, vertical, Wakefield 634-xxABP, small PCB footprint.
IC1 IC6 IC14 IC19 IC24 = QuantumOptics:AD8212(CURRENT_MONITOR): AD8212 Current Sense Monitor, Analog Devices, 7-65V, current output. http://www.analog.com/UploadedFiles/Data_Sheets/AD8212.pdf
IC2-IC5 IC7-IC10 IC13 IC15-IC18 IC20-IC23 IC25-IC27 = QuantumOptics:OPAMP: Op Amp, generic, pick the right package. e.g. AD8605: SOT-23-5, RRIO, 10MHz, Ib = 1pA, Vio < 65uV, 2.7-5.5V.
IC11 = QuantumOptics:LM1086: LM1086-xxx, National Semiconductor, LDO, adjustable or fixed. http://cache.national.com/ds/LM/LM1086.pdf
IC12 = QuantumOptics:ADR43_(REFERENCE): ADR43x Reference, regulator style with trim, 2V to 5V, sink or source, 3-10PPM/°. http://www.analog.com/UploadedFiles/Data_Sheets/ADR430_431_433_434_435_439.pdf
J1-J5 = QuantumOptics:CONN-BNC: BNC PCB, horizontal, Amp 227677-1, nut 1-329631-2, shoulder washer 330620. The two shield connections allow the assembly on either side of the board. http://catalog.tycoelectronics.com/TE/bin/TE.Connect?C=1&PN=227677-1&M=STARTSWITH&LG=1&I=13&button.x=0&button.y=0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
P1 = QuantumOptics:CONN-DB9: D-Type DB-9, AKA DB-9.
Q1-Q10 = QuantumOptics:BJT-NPN: NPN BJT, generic, p/n defined by VALUE field. E.g. Fairchild MMBT5551 (abs max 160V, 600mA. hFE>80@10mA.
Q11 = QuantumOptics:MOSFET-N: Mosfet, N-Channel, generic enhancement mode N-FET.
R1 R2 R8 R9 R11 R12 R14 R15 R17 R19 R20 R26 R27 R29 R30 R32 R33 R35 R37 R38 R41 R42 R44 R46 R52 R54-R57 R59 R60 R62 R64 R70 R72-R75 R77 R78 R80 R82 R88 R90-R95 R97 = QuantumOptics:R-V-*: Resistor, SMT & Through-Hole, vertical symbol
R3 R5-R7 R10 R13 R16 R18 R21 R23-R25 R28 R31 R34 R36 R39 R40 R43 R47-R51 R53 R58 R61 R65-R69 R71 R76 R79 R83-R87 R89 R98-R108 = QuantumOptics:R-H-*: Resistor, SMT & Through-Hole, horizontal symbol
R4 R22 R45 R63 R81 = QuantumOptics:R-SENSE: Current sense resistor, 4-terminal. e.g. Ohmite series 60, http://www.ohmite.com/cgi-bin/showpage.cgi?product=60-4_series
R96 = QuantumOptics:POT: Pot, regular or trimpot
TP1-TP26 = QuantumOptics:TP4: Terminal block or connection with 4 holes, based on Pheonix 1987054.

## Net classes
0 default: drill 0.406 mm
1 Power: width 1.016 mm, drill 3.175 mm, clearance 0.178 mm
